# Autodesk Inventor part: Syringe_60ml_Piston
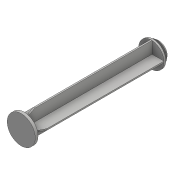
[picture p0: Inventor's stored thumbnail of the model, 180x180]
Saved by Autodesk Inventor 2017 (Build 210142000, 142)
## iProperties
Created: 2018-03
Part Number: Syringe_60ml_Piston
Material: Generic
Document SubType Name: Modeling
Designer: JK
Density: 1 g/cm^3
Appearance: Default
Title: C:/Users/Marco/Documents/Marco/3D printing/Syringe_60ml_Piston.step
Sending System: Autodesk Translation Framework v6.5.0.72
Preprocessor: ST-DEVELOPER v16.13
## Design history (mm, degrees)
feature "Body1"
body "Solid1"
